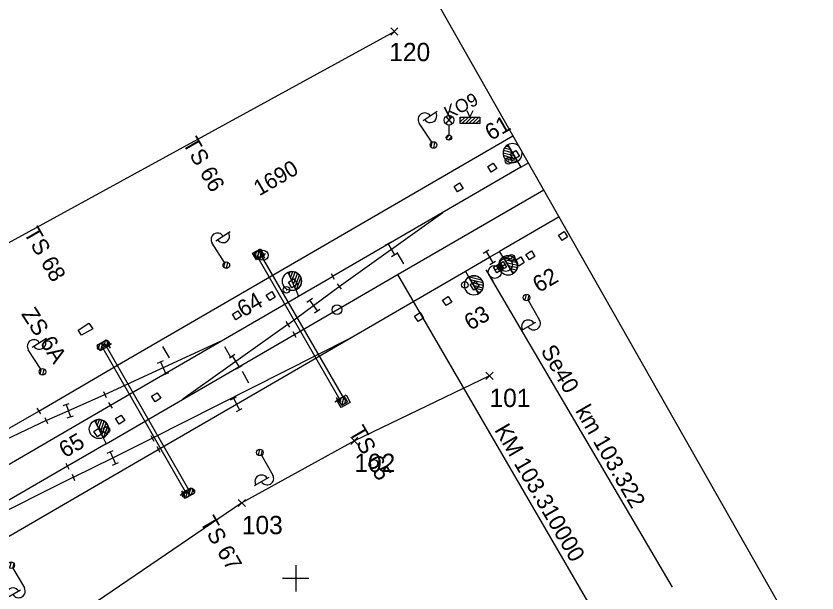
# Model space of a CAD drawing. Extents: x -566182 to -565305, y -1203073 to -1202401.
# Drawn here: x -565642.7 to -565520.4, y -1202702.3 to -1202614.1 of the extents above; entities that cross this region are included whole.
import ezdxf

# ---------------------------------------------------------------- set-up
doc = ezdxf.new("R2010")
doc.units = 0
for name, color, linetype in [('CD', 7, 'Continuous'), ('Vrstva 1', 7, 'Continuous'), ('Vrstva 10', 7, 'Continuous'), ('Vrstva 12', 7, 'Continuous'), ('Vrstva 13', 7, 'Continuous'), ('Vrstva 16', 7, 'Continuous'), ('Vrstva 17', 7, 'Continuous'), ('Vrstva 18', 7, 'Continuous'), ('Vrstva 22', 7, 'Continuous'), ('Vrstva 24', 7, 'Continuous'), ('Vrstva 25', 7, 'Continuous'), ('Vrstva 39', 7, 'Continuous'), ('Vrstva 40', 7, 'Continuous'), ('Vrstva 5', 7, 'Continuous'), ('Vrstva 6', 7, 'Continuous'), ('Vrstva 60', 7, 'Continuous'), ('Vrstva 62', 7, 'Continuous'), ('Vrstva 63', 7, 'Continuous'), ('Vrstva 8', 7, 'Continuous'), ('Vrstva 9', 7, 'Continuous')]:
    doc.layers.add(name, color=color, linetype=linetype)

# ---------------------------------------------------------------- blocks, each defined once
blk = doc.blocks.new('EOV')
at = {"layer": 'Vrstva 62'}
blk.add_lwpolyline([(-5, 5), (5, 5), (5, -5), (-5, -5)], close=True, dxfattribs=at)
blk = doc.blocks.new('C513')
at = {"layer": 'Vrstva 6'}
blk.add_circle((0, 0), 7.5, dxfattribs=at)
blk = doc.blocks.new('C84')
at = {"layer": 'Vrstva 8'}
blk.add_line((0, 5), (0, -5), dxfattribs=at)
blk = doc.blocks.new('C649')
at = {"layer": 'Vrstva 18'}
for p, q in [((-5, 10), (5, 10)), ((0, 10), (0, -10)), ((-5, -10), (5, -10))]:
    blk.add_line(p, q, dxfattribs=at)
blk = doc.blocks.new('C53')
at = {"layer": 'Vrstva 22'}
blk.add_line((-0.5, 0), (0.5, 0), dxfattribs=at)
blk.add_circle((0, 0), 5, dxfattribs=at)
blk = doc.blocks.new('C515_5')
at = {"layer": 'Vrstva 8'}
for p, q in [((0, 39.6), (0, 10.3)), ((0, 35.8), (3.3, 39.1)), ((0, 30.5), (7.2, 37.6)), ((0, 25.2), (10.2, 35.4)), ((0, 19.8), (12.5, 32.4)), ((0, 14.5), (14.1, 28.7)), ((1.1, 10.4), (14.5, 23.8)), ((0, 10.3), (0, 0))]:
    blk.add_line(p, q, dxfattribs=at)
for points in [[(0, 10.3), (0, 39.6)], [(0, 10.3), (0, 10.3)]]:
    blk.add_lwpolyline(points, dxfattribs=at)
blk.add_circle((0, 25), 14.6, dxfattribs=at)
blk.add_arc((0, 24.9), 14.6, 270.0221, 89.9829, dxfattribs=at)
blk = doc.blocks.new('C515_6')
at = {"layer": 'Vrstva 8'}
for p, q in [((0, 39.6), (0, 10.3)), ((0, 35.8), (3.4, 39.1)), ((0, 30.5), (7.2, 37.6)), ((0, 25.2), (10.2, 35.4)), ((0, 19.8), (12.5, 32.4)), ((0, 14.5), (14.1, 28.7)), ((1.1, 10.4), (14.5, 23.8)), ((0, 10.3), (0, 0))]:
    blk.add_line(p, q, dxfattribs=at)
for points in [[(0, 10.3), (0, 39.6)], [(0, 10.3), (0, 10.3)]]:
    blk.add_lwpolyline(points, dxfattribs=at)
blk.add_circle((0, 25), 14.6, dxfattribs=at)
blk.add_arc((0, 24.9), 14.6, 270.0155, 89.9763, dxfattribs=at)
blk = doc.blocks.new('C515_7')
at = {"layer": 'Vrstva 8'}
for p, q in [((0, 39.6), (0, 10.3)), ((0, 35.8), (3.3, 39.1)), ((0, 30.4), (7.2, 37.6)), ((0, 25.2), (10.2, 35.4)), ((0, 19.8), (12.5, 32.4)), ((0, 14.5), (14.1, 28.7)), ((1.1, 10.4), (14.5, 23.8)), ((0, 10.3), (0, 0))]:
    blk.add_line(p, q, dxfattribs=at)
for points in [[(0, 10.3), (0, 39.6), (0, 39.6)], [(0, 10.3), (0, 10.3), (0, 10.3)]]:
    blk.add_lwpolyline(points, dxfattribs=at)
blk.add_circle((0, 25), 14.6, dxfattribs=at)
blk.add_arc((0, 24.9), 14.6, 270.0194, 89.9803, dxfattribs=at)
blk = doc.blocks.new('C515_8')
at = {"layer": 'Vrstva 8'}
for p, q in [((0, 39.6), (0, 10.3)), ((0, 35.8), (3.4, 39.1)), ((0, 30.5), (7.2, 37.6)), ((0, 25.2), (10.2, 35.4)), ((0, 19.8), (12.5, 32.4)), ((0, 14.6), (14.1, 28.7)), ((1.1, 10.4), (14.5, 23.8)), ((0, 10.3), (0, 0))]:
    blk.add_line(p, q, dxfattribs=at)
for points in [[(0, 10.3), (0, 39.6)], [(0, 10.3), (0, 10.3)]]:
    blk.add_lwpolyline(points, dxfattribs=at)
blk.add_circle((0, 25), 14.6, dxfattribs=at)
blk.add_arc((0, 24.9), 14.6, 270.0329, 89.9937, dxfattribs=at)
blk = doc.blocks.new('C691')
at = {"layer": 'Vrstva 12'}
for p, q in [((-5, 0), (5, 0)), ((0, 5), (0, -5))]:
    blk.add_line(p, q, dxfattribs=at)
blk = doc.blocks.new('C669')
at = {"layer": 'Vrstva 6'}
for p, q in [((0, 5), (0, 40)), ((7, 40), (33, 40)), ((-5, -1), (1, 5)), ((-2, -4), (4, 2))]:
    blk.add_line(p, q, dxfattribs=at)
blk.add_circle((0, 0), 5, dxfattribs=at)
blk.add_circle((0, 0), 5, dxfattribs=at)
for centre, start, end in [((10, 40), 0.0001, 180.0001), ((20, 39.9), 179.2975, 0.7026)]:
    blk.add_arc(centre, 10, start, end, dxfattribs=at)
blk = doc.blocks.new('C669_1')
at = {"layer": 'Vrstva 6'}
for p, q in [((0, 5), (0, 40)), ((7, 40), (33, 40)), ((-5, -1), (1, 5)), ((-2, -4), (4, 2))]:
    blk.add_line(p, q, dxfattribs=at)
blk.add_circle((0, 0), 5, dxfattribs=at)
blk.add_circle((0, 0), 5, dxfattribs=at)
for centre, start, end in [((10, 40), 0, 180), ((20, 39.9), 179.2975, 0.7026)]:
    blk.add_arc(centre, 10, start, end, dxfattribs=at)
blk = doc.blocks.new('C202_2')
at = {"layer": 'Vrstva 8'}
blk.add_lwpolyline([(-10, 0.5), (-10.1, 9.8), (9.8, 10.1), (10, -0.5), (-10, 0.5)], dxfattribs=at)
blk = doc.blocks.new('C661_2')
at = {"layer": 'Vrstva 12'}
for p, q in [((-5, 0.3), (-0.3, 5)), ((-5, -5), (5, 5)), ((0.3, -5), (5, -0.3))]:
    blk.add_line(p, q, dxfattribs=at)
blk.add_lwpolyline([(-5, 5), (5, 5), (5, -5), (-5, -5)], close=True, dxfattribs=at)
blk.add_lwpolyline([(-5, 5), (5, 5), (5, -5), (-5, -5), (-5, 5)], dxfattribs=at)
blk = doc.blocks.new('C663_2')
at = {"layer": 'Vrstva 12'}
for p, q in [((-9.7, -1.6), (-3.4, 4.7)), ((-7.3, -4.4), (-0.6, 2.3)), ((0.3, -1.6), (6.6, 4.7)), ((2.8, -4.4), (9.4, 2.2))]:
    blk.add_line(p, q, dxfattribs=at)
for centre in [(-5, 0), (-5, 0), (5, 0), (5, 0)]:
    blk.add_circle(centre, 5, dxfattribs=at)
blk = doc.blocks.new('C663_3')
at = {"layer": 'Vrstva 12'}
for p, q in [((-9.7, -1.6), (-3.4, 4.7)), ((-7.3, -4.4), (-0.6, 2.3)), ((0.3, -1.6), (6.6, 4.7)), ((2.8, -4.4), (9.4, 2.2))]:
    blk.add_line(p, q, dxfattribs=at)
for centre in [(-5, 0), (-5, 0), (5, 0), (5, 0)]:
    blk.add_circle(centre, 5, dxfattribs=at)
blk = doc.blocks.new('C187')
at = {"layer": 'Vrstva 6'}
for p, q in [((-4.9, 32.1), (5, 20.9)), ((-4.8, 20.8), (5.1, 32)), ((0, 19), (0, 4)), ((-3.9, -0.8), (0.8, 3.9)), ((-1.2, -3.8), (3.8, 1.2))]:
    blk.add_line(p, q, dxfattribs=at)
for centre, radius in [((0, 26.5), 7.49), ((0, 0), 4), ((0, 0), 4)]:
    blk.add_circle(centre, radius, dxfattribs=at)
blk = doc.blocks.new('C534')
at = {"layer": 'Vrstva 16'}
for p, q in [((-15, 2.8), (-12.8, 5)), ((-15, -2.5), (-7.5, 5)), ((-12.2, -5), (-2.2, 5)), ((-6.9, -5), (3.1, 5)), ((-1.6, -5), (8.4, 5)), ((3.7, -5), (13.7, 5)), ((9, -5), (15, 1)), ((14.3, -5), (15, -4.3))]:
    blk.add_line(p, q, dxfattribs=at)
for points in [[(-5, 15), (0, 5), (5, 15)], [(-15, 5), (15, 5), (15, -5), (-15, -5), (-15, 5)]]:
    blk.add_lwpolyline(points, dxfattribs=at)
blk.add_lwpolyline([(-15, 5), (15, 5), (15, -5), (-15, -5)], close=True, dxfattribs=at)
blk = doc.blocks.new('C575_2')
at = {"layer": 'Vrstva 24'}
blk.add_line((0, 10), (0, -10), dxfattribs=at)
for centre in [(10, 0), (30, 0)]:
    blk.add_circle(centre, 10, dxfattribs=at)
blk = doc.blocks.new('STTRAN')
at = {"layer": 'Vrstva 40'}
for p, q in [((-5, 0), (5, 0)), ((0, 5), (0, -5))]:
    blk.add_line(p, q, dxfattribs=at)
blk.add_lwpolyline([(-5, 5), (5, 5), (5, -5), (-5, -5)], close=True, dxfattribs=at)
blk = doc.blocks.new('EOV_1')
at = {"layer": 'Vrstva 40'}
blk.add_lwpolyline([(-5, 5), (5, 5), (5, -5), (-5, -5)], close=True, dxfattribs=at)

msp = doc.modelspace()

# ---------------------------------------------------------------- linework, layer by layer
at = {"layer": 'CD'}
for p, q in [((-565651.82, -1202653.08), (-565584.94, -1202616.47)), ((-565570.41, -1202669.07), (-565591.05, -1202679)), ((-565591.05, -1202679), (-565608.23, -1202688.5)), ((-565608.23, -1202688.5), (-565651.3, -1202717.76))]:
    msp.add_line(p, q, dxfattribs=at)
at = {"layer": 'Vrstva 1'}
msp.add_lwpolyline([(-566031.4, -1203059.85), (-565496.48, -1202756.39), (-565633.16, -1202515.46), (-566168.08, -1202818.92)], close=True, dxfattribs=at)
at = {"layer": 'Vrstva 10'}
for p, q in [((-565606.59, -1202650.35), (-565605.4, -1202649.67)), ((-565605.4, -1202649.67), (-565604.84, -1202650.68)), ((-565606.01, -1202651.37), (-565606.59, -1202650.35)), ((-565604.84, -1202650.68), (-565606.01, -1202651.37)), ((-565630.34, -1202664.39), (-565628.94, -1202663.57)), ((-565628.94, -1202663.57), (-565628.44, -1202664.42)), ((-565629.89, -1202665.26), (-565630.34, -1202664.39)), ((-565628.44, -1202664.42), (-565629.89, -1202665.26)), ((-565593.71, -1202672.78), (-565592.32, -1202672)), ((-565592.32, -1202672), (-565591.69, -1202673.16)), ((-565593.07, -1202673.93), (-565593.71, -1202672.78)), ((-565591.69, -1202673.16), (-565593.07, -1202673.93)), ((-565617.41, -1202686.97), (-565615.95, -1202686.17)), ((-565615.95, -1202686.17), (-565615.45, -1202687)), ((-565616.88, -1202687.83), (-565617.41, -1202686.97)), ((-565615.45, -1202687), (-565616.88, -1202687.83))]:
    msp.add_line(p, q, dxfattribs=at)
for points in [[(-565583.49, -1202651.95), (-565584.49, -1202650.23)], [(-565619.26, -1202666.31), (-565620.3, -1202664.61)], [(-565609.88, -1202666.38), (-565610.82, -1202664.62)], [(-565607.18, -1202670.17), (-565608.12, -1202668.41)]]:
    msp.add_lwpolyline(points, dxfattribs=at)
at = {"layer": 'Vrstva 12'}
for points in [[(-565593.04, -1202673.05), (-565605.96, -1202650.68)], [(-565592.52, -1202672.75), (-565605.44, -1202650.38)], [(-565616.64, -1202687.13), (-565629.62, -1202664.55)], [(-565616.12, -1202686.83), (-565629.1, -1202664.25)]]:
    msp.add_lwpolyline(points, dxfattribs=at)
at = {"layer": 'Vrstva 5'}
for p, q in [((-565600, -1202698), (-565600, -1202702)), ((-565602, -1202700), (-565598, -1202700))]:
    msp.add_line(p, q, dxfattribs=at)
at = {"layer": 'Vrstva 6'}
for points in [[(-565639.25, -1202674.45), (-565628.18, -1202668.02), (-565603.34, -1202653.59), (-565566.83, -1202632.39)], [(-565565.64, -1202637.2), (-565564.48, -1202636.53)], [(-565600.21, -1202662.74), (-565584.34, -1202653.53), (-565562.14, -1202640.64)], [(-565574.1, -1202653.09), (-565570.43, -1202650.96), (-565568.89, -1202650.06)], [(-565599.56, -1202656.88), (-565594.37, -1202653.87)], [(-565601.22, -1202661.21), (-565597.31, -1202658.33), (-565593.37, -1202655.41)], [(-565638.11, -1202675.88), (-565634.74, -1202674.4), (-565629.13, -1202671.93)], [(-565772.18, -1202757.12), (-565716.36, -1202724.73), (-565690.38, -1202709.64), (-565661.87, -1202693.06), (-565648.68, -1202685.41), (-565628.31, -1202673.57)], [(-565628.96, -1202679.45), (-565634.87, -1202682.87)], [(-565633.95, -1202684.58), (-565627.92, -1202681.59), (-565621.9, -1202678.62)], [(-565685.66, -1202717.86), (-565678.55, -1202713.73), (-565657.5, -1202701.52), (-565621, -1202680.32)]]:
    msp.add_lwpolyline(points, dxfattribs=at)
at = {"layer": 'Vrstva 60'}
for p, q in [((-565584.49, -1202616.92), (-565585.49, -1202615.92)), ((-565585.39, -1202616.92), (-565584.39, -1202615.92)), ((-565584.49, -1202616.02), (-565585.49, -1202617.02)), ((-565585.39, -1202616.02), (-565584.39, -1202617.02)), ((-565584.94, -1202616.47), (-565584.94, -1202616.47)), ((-565584.45, -1202653.59), (-565544.48, -1202722.42)), ((-565570.45, -1202653.73), (-565542.51, -1202701.35)), ((-565569.96, -1202669.52), (-565570.96, -1202668.52)), ((-565570.86, -1202669.52), (-565569.86, -1202668.52)), ((-565569.96, -1202668.62), (-565570.96, -1202669.62)), ((-565570.86, -1202668.62), (-565569.86, -1202669.62)), ((-565570.41, -1202669.07), (-565570.41, -1202669.07)), ((-565590.6, -1202679.45), (-565591.6, -1202678.45)), ((-565590.6, -1202678.55), (-565591.6, -1202679.55)), ((-565591.5, -1202679.45), (-565590.5, -1202678.45)), ((-565591.5, -1202678.55), (-565590.5, -1202679.55)), ((-565591.05, -1202679), (-565591.05, -1202679)), ((-565607.78, -1202688.95), (-565608.78, -1202687.95)), ((-565607.78, -1202688.05), (-565608.78, -1202689.05)), ((-565608.68, -1202688.95), (-565607.68, -1202687.95)), ((-565608.68, -1202688.05), (-565607.68, -1202689.05)), ((-565608.23, -1202688.5), (-565608.23, -1202688.5))]:
    msp.add_line(p, q, dxfattribs=at)
at = {"layer": 'Vrstva 63'}
msp.add_line((-565605.02, -1202650.67), (-565604.93, -1202650.62), dxfattribs=at)
msp.add_circle((-565604.97, -1202650.65), 0.756, dxfattribs=at)
at = {"layer": 'Vrstva 8'}
for p, q in [((-565567.43, -1202634.11), (-565567.89, -1202633.98)), ((-565567.62, -1202633.78), (-565566.16, -1202636.31)), ((-565566.63, -1202635.48), (-565568.35, -1202635.03)), ((-565566.9, -1202635.02), (-565568.3, -1202634.65)), ((-565566.37, -1202635.94), (-565568.3, -1202635.43)), ((-565567.17, -1202634.56), (-565568.15, -1202634.3)), ((-565566.26, -1202636.36), (-565568.09, -1202635.87)), ((-565566.15, -1202636.31), (-565565.64, -1202637.2))]:
    msp.add_line(p, q, dxfattribs=at)
for points in [[(-565566.15, -1202636.31), (-565567.62, -1202633.78)], [(-565566.16, -1202636.31), (-565566.15, -1202636.31)], [(-565565.64, -1202637.2), (-565594.37, -1202653.87)], [(-565593.37, -1202655.41), (-565577.53, -1202644.1)], [(-565559.8, -1202644.78), (-565568.89, -1202650.06)], [(-565621, -1202680.32), (-565609.06, -1202673.39), (-565574.1, -1202653.09)], [(-565628.31, -1202673.57), (-565599.56, -1202656.88)], [(-565601.22, -1202661.21), (-565617.22, -1202672.62)], [(-565628.96, -1202679.45), (-565600.21, -1202662.74)], [(-565621.9, -1202678.62), (-565591.58, -1202663.24)], [(-565629.13, -1202671.93), (-565611.49, -1202663.8)], [(-565667.5, -1202690.78), (-565649.91, -1202680.6), (-565639.25, -1202674.45)], [(-565638.11, -1202675.88), (-565658.7, -1202685.69)], [(-565634.87, -1202682.87), (-565681.75, -1202710.09)], [(-565633.95, -1202684.58), (-565661.78, -1202698.5)]]:
    msp.add_lwpolyline(points, dxfattribs=at)
for start, end in [(50.7333, 8.3998), (120.1089, 300.0697)]:
    msp.add_arc((-565566.89, -1202635.04), 1.46, start, end, dxfattribs=at)

# ---------------------------------------------------------------- block references
at = {"layer": 'Vrstva 12'}
for name, p, xscale, yscale, rotation in [('C661_2', (-565605.7, -1202650.53), 0.09999983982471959, 0.09999983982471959, 30.622180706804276), ('C691', (-565605.04, -1202650.65), 0.09999990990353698, 0.09999990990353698, 30.000029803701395), ('C663_2', (-565629.36, -1202664.4), 0.09999991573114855, 0.09999991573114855, 30.246181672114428), ('C691', (-565628.59, -1202664.39), 0.09999990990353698, 0.09999990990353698, 30.000029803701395), ('C691', (-565628.59, -1202664.4), 0.09999990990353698, 0.09999990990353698, 30.000029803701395), ('C691', (-565593.58, -1202672.79), 0.09999990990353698, 0.09999990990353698, 30.000029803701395), ('C661_2', (-565592.78, -1202672.9), 0.09999993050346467, 0.09999993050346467, 29.155747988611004), ('C691', (-565617.21, -1202687.06), 0.09999990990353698, 0.09999990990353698, 30.000029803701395), ('C663_3', (-565616.38, -1202686.98), 0.1000001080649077, 0.1000001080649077, 28.89694107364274)]:
    msp.add_blockref(name, p, dxfattribs=dict(at, xscale=xscale, yscale=yscale, rotation=rotation))
at = {"layer": 'Vrstva 16', "xscale": 0.1, "yscale": 0.10000000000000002}
msp.add_blockref('C534', (-565573.4, -1202630.03), dxfattribs=at)
at = {"layer": 'Vrstva 18'}
for p, xscale, yscale, rotation in [((-565585.43, -1202649.74), 0.10000008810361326, 0.10000008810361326, 30.17264568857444), ((-565570.43, -1202650.96), 0.09999989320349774, 0.09999989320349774, 30.18413015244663), ((-565597.31, -1202658.33), 0.0999998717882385, 0.0999998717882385, 34.558472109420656), ((-565609.18, -1202666.89), 0.10000008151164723, 0.10000008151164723, 31.49229844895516), ((-565620.25, -1202667.84), 0.09999978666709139, 0.0999997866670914, 23.965631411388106), ((-565634.74, -1202674.4), 0.10000007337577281, 0.10000007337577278, 18.638873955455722), ((-565609.06, -1202673.39), 0.10000010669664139, 0.10000010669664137, 26.471624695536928), ((-565627.92, -1202681.59), 0.10000012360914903, 0.10000012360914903, 24.464335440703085)]:
    msp.add_blockref('C649', p, dxfattribs=dict(at, xscale=xscale, yscale=yscale, rotation=rotation))
at = {"layer": 'Vrstva 22', "xscale": 0.1, "yscale": 0.10000000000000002}
for p in [(-565567.5, -1202636.23), (-565567.05, -1202651.04), (-565574.19, -1202655.19), (-565601.4, -1202655.93), (-565628.88, -1202677.35)]:
    msp.add_blockref('C53', p, dxfattribs=at)
at = {"layer": 'Vrstva 24', "xscale": 0.09999982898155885, "yscale": 0.09999982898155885, "rotation": 32.548788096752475}
msp.add_blockref('C575_2', (-565570.45, -1202653.73), dxfattribs=at)
at = {"layer": 'Vrstva 40'}
for name, p, xscale, yscale, rotation in [('EOV_1', (-565566.55, -1202635.34), 0.10000003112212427, 0.10000003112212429, 32.99994277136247), ('EOV_1', (-565569.99, -1202637.25), 0.10000003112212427, 0.10000003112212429, 32.99994277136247), ('EOV_1', (-565575.14, -1202640.29), 0.10000003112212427, 0.10000003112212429, 32.99994277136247), ('EOV_1', (-565559.17, -1202647.71), 0.10000003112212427, 0.10000003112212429, 32.99994277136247), ('EOV_1', (-565564.17, -1202650.68), 0.10000003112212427, 0.10000003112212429, 32.99994277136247), ('EOV_1', (-565565.79, -1202651.6), 0.10000003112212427, 0.10000003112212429, 32.99994277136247), ('STTRAN', (-565569.13, -1202652.65), 0.09999990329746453, 0.09999990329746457, 30.059200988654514), ('STTRAN', (-565568.49, -1202652.31), 0.09999990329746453, 0.09999990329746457, 30.059200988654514), ('EOV_1', (-565600.44, -1202654.93), 0.10000003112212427, 0.10000003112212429, 32.99994277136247), ('EOV_1', (-565572.68, -1202655.28), 0.10000003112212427, 0.10000003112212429, 32.99994277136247), ('EOV_1', (-565603.82, -1202656.89), 0.10000003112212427, 0.10000003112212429, 32.99994277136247), ('EOV_1', (-565576.88, -1202657.65), 0.10000003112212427, 0.10000003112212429, 32.99994277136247), ('EOV_1', (-565608.99, -1202659.82), 0.10000003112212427, 0.10000003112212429, 32.99994277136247), ('EOV_1', (-565581.17, -1202660.1), 0.10000003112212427, 0.10000003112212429, 32.99994277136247), ('EOV_1', (-565621.31, -1202672.34), 0.10000003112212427, 0.10000003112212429, 32.99994277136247), ('EOV_1', (-565626.81, -1202675.75), 0.10000003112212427, 0.10000003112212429, 32.99994277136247), ('EOV_1', (-565630.15, -1202677.71), 0.10000003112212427, 0.10000003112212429, 32.99994277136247)]:
    msp.add_blockref(name, p, dxfattribs=dict(at, xscale=xscale, yscale=yscale, rotation=rotation))
at = {"layer": 'Vrstva 6'}
for name, p, xscale, yscale, rotation in [('C669', (-565578.97, -1202633.8), 0.10000003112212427, 0.10000003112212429, 32.99994277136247), ('C669', (-565610.6, -1202652.16), 0.10000003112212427, 0.10000003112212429, 32.99994277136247), ('C669_1', (-565564.77, -1202657.09), 0.09999990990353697, 0.099999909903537, -149.99997019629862), ('C513', (-565593.7, -1202658.96), 0.1, 0.10000000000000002, 180), ('C669', (-565638.66, -1202668.45), 0.10000003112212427, 0.10000003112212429, 32.99994277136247), ('C669_1', (-565605.5, -1202680.77), 0.09999990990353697, 0.099999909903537, -149.99997019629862), ('C669_1', (-565643.44, -1202698.01), 0.09999990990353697, 0.099999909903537, -149.99997019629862)]:
    msp.add_blockref(name, p, dxfattribs=dict(at, xscale=xscale, yscale=yscale, rotation=rotation))
at = {"layer": 'Vrstva 6', "xscale": 0.1, "yscale": 0.10000000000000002}
msp.add_blockref('C187', (-565576.61, -1202632.66), dxfattribs=at)
at = {"layer": 'Vrstva 62', "xscale": 0.10000003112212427, "yscale": 0.10000003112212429, "rotation": 32.99994277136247}
for p in [(-565566.55, -1202635.34), (-565569.99, -1202637.25), (-565575.14, -1202640.29), (-565559.17, -1202647.71), (-565564.17, -1202650.68), (-565565.79, -1202651.6), (-565600.44, -1202654.93), (-565572.68, -1202655.28), (-565603.82, -1202656.89), (-565576.88, -1202657.65), (-565608.99, -1202659.82), (-565581.17, -1202660.1), (-565621.31, -1202672.34), (-565626.81, -1202675.75), (-565630.15, -1202677.71)]:
    msp.add_blockref('EOV', p, dxfattribs=at)
at = {"layer": 'Vrstva 8'}
for name, p, xscale, yscale, rotation in [('C515_8', (-565568.89, -1202650.06), 0.10000047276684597, -0.10000047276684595, 31.67757507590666), ('C515_7', (-565574.1, -1202653.09), 0.10000005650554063, -0.10000005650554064, 30.839069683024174), ('C515_6', (-565599.56, -1202656.88), 0.10000007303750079, 0.10000007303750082, 24.099645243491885), ('C84', (-565594.37, -1202653.87), 0.0999998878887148, 0.09999988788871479, 27.396732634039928), ('C84', (-565593.37, -1202655.41), 0.09999994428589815, 0.09999994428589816, 35.141700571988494), ('C202_2', (-565631.86, -1202662.38), 0.10000003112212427, 0.10000003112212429, 32.99994277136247), ('C84', (-565601.22, -1202661.21), 0.09999996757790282, 0.09999996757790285, 33.132407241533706), ('C84', (-565600.21, -1202662.74), 0.09999995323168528, 0.09999995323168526, 28.475459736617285), ('C84', (-565629.13, -1202671.93), 0.09999992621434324, 0.09999992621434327, 24.262294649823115), ('C84', (-565628.31, -1202673.57), 0.10000021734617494, 0.10000021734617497, 31.59493490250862), ('C84', (-565639.25, -1202674.45), 0.100000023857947, 0.100000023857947, 33.462448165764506), ('C84', (-565638.11, -1202675.88), 0.10000021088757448, 0.10000021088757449, 25.044278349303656), ('C515_5', (-565628.96, -1202679.45), 0.09999991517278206, 0.09999991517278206, 26.086935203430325), ('C84', (-565621.9, -1202678.62), 0.09999984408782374, 0.09999984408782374, 25.359006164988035), ('C84', (-565621, -1202680.32), 0.10000012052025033, 0.10000012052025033, 28.20924786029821), ('C84', (-565634.87, -1202682.87), 0.10000008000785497, 0.10000008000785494, 25.91916590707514), ('C84', (-565633.95, -1202684.58), 0.09999992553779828, 0.09999992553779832, 22.377769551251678)]:
    msp.add_blockref(name, p, dxfattribs=dict(at, xscale=xscale, yscale=yscale, rotation=rotation))

# ---------------------------------------------------------------- texts
at = {"layer": 'Vrstva 13'}
for s, p in [('TS 66', (-565617.34, -1202633.5)), ('TS 68', (-565641.61, -1202647.22)), ('TS 65', (-565591.89, -1202677.59)), ('TS 67', (-565614.71, -1202691.39))]:
    msp.add_text(s, height=2.5, rotation=300, dxfattribs=at).set_placement(p)
at = {"layer": 'Vrstva 17'}
msp.add_text('KO9', height=2, rotation=27.1631, dxfattribs=at).set_placement((-565576.69, -1202629.94))
at = {"layer": 'Vrstva 25'}
msp.add_text('Se40   km 103.322', height=2.5, rotation=299.9873, dxfattribs=at).set_placement((-565562.67, -1202665.22))
at = {"layer": 'Vrstva 39'}
msp.add_text('KM 103.310000', height=2.5, rotation=300.145, dxfattribs=at).set_placement((-565569.73, -1202677.32))
at = {"layer": 'Vrstva 60'}
for s, p in [('120', (-565585.72, -1202620.99)), ('101', (-565570.41, -1202673.84)), ('102', (-565591.05, -1202683.77)), ('103', (-565608.23, -1202693.27))]:
    msp.add_text(s, height=2.8, dxfattribs=at).set_placement(p)
at = {"layer": 'Vrstva 63'}
msp.add_text('1690', height=2.4, rotation=30.147, dxfattribs=at).set_placement((-565605.55, -1202641.65))
at = {"layer": 'Vrstva 9'}
for s, rotation, p in [('61', 30.1448, (-565570.18, -1202633.2)), ('62', 30.1448, (-565562.89, -1202656.43)), ('64', 30.1447, (-565608.01, -1202660.18)), ('ZS 6A', 303, (-565641.99, -1202659.63)), ('63', 30.1448, (-565573.35, -1202662.21)), ('65', 30.1448, (-565635.23, -1202681.68))]:
    msp.add_text(s, height=2.5, rotation=rotation, dxfattribs=at).set_placement(p)

doc.saveas('drawing.dxf')
